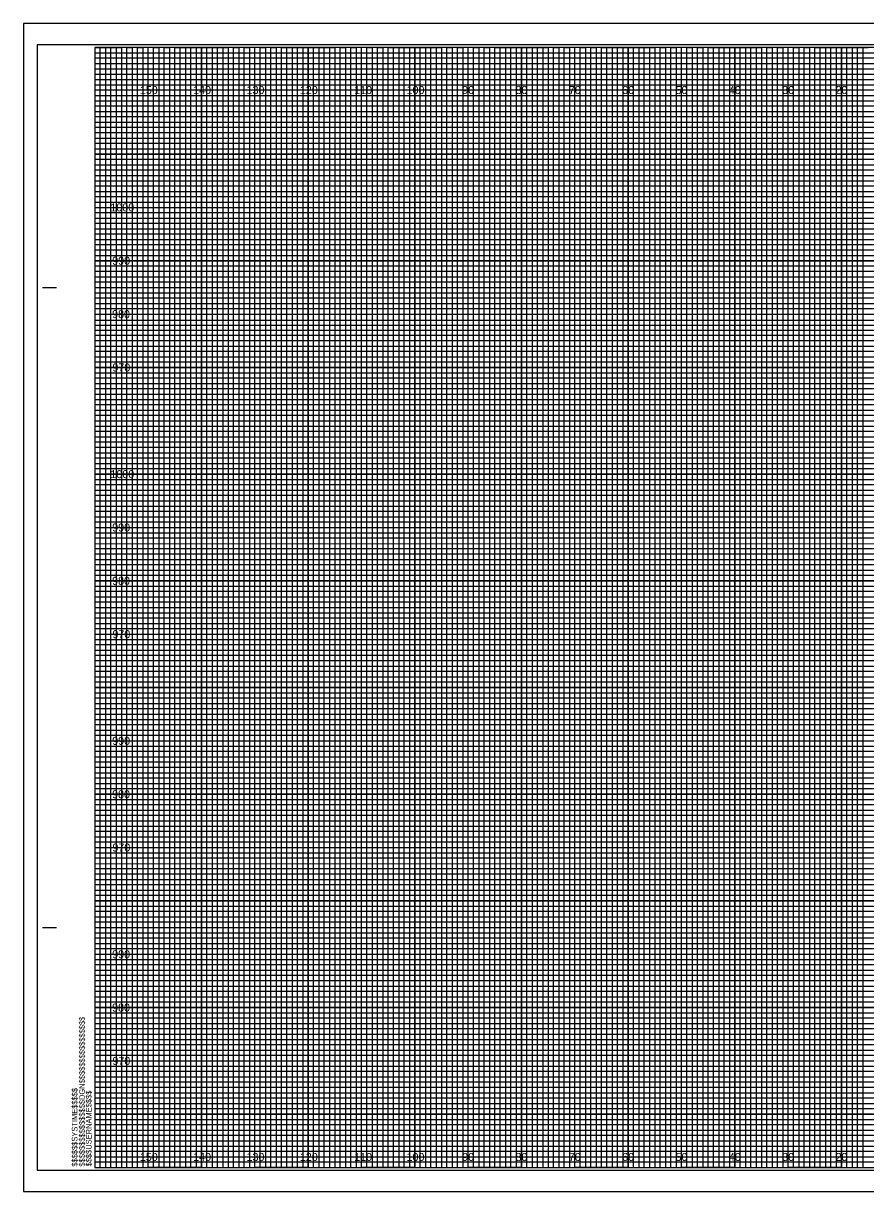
# Model space of a CAD drawing. Extents: x -13 to 323, y -5 to 215.
# Drawn here: x -13.4 to 144.5, y -4.5 to 214.5 of the extents above; entities that cross this region are included whole.
import ezdxf

# ---------------------------------------------------------------- set-up
doc = ezdxf.new("R2010")
doc.units = 0
for name, color, linetype in [('Prop XS Elevation Labels', 7, 'Continuous'), ('Prop XS Offset Labels', 7, 'Continuous'), ('Sheet Cross Section CELL', 7, 'Continuous'), ('Sheet Cross Section Grid Major CELL', 7, 'Continuous'), ('Sheet Cross Section Grid Middle CELL', 7, 'Continuous'), ('Sheet Cross Section Grid Minor 1 CELL', 7, 'Continuous'), ('Sheet Cross Section Grid Minor 2 CELL', 7, 'Continuous'), ('Sheet Cutting Line CELL', 7, 'Continuous'), ('Sheet DOT Grid CELL', 7, 'Continuous'), ('Sheet Plot Border Inside CELL', 7, 'Continuous'), ('Sheet Plot Border Outside CELL', 7, 'Continuous')]:
    doc.layers.add(name, color=color, linetype=linetype)

msp = doc.modelspace()

# ---------------------------------------------------------------- linework, layer by layer
at = {"layer": 'Sheet Cross Section CELL'}
for p, q in [((-9.8, 165), (-7.3, 165)), ((-9.7, 165), (-7.2, 165)), ((-9.8, 45), (-7.3, 45)), ((-9.7, 45), (-7.2, 45))]:
    msp.add_line(p, q, dxfattribs=at)
msp.add_lwpolyline([(320, 210), (0, 210), (0, 0), (320, 0)], close=True, dxfattribs=at)
at = {"layer": 'Sheet Cross Section Grid Major CELL'}
for p, q in [((10, 210), (0, 210)), ((10, 0), (10, 210)), ((30, 210), (20, 210)), ((20, 210), (20, 0)), ((30, 0), (30, 210)), ((50, 210), (40, 210)), ((40, 210), (40, 0)), ((50, 0), (50, 210)), ((70, 210), (60, 210)), ((60, 210), (60, 0)), ((70, 0), (70, 210)), ((90, 210), (80, 210)), ((80, 210), (80, 0)), ((90, 0), (90, 210)), ((110, 210), (100, 210)), ((100, 210), (100, 0)), ((110, 0), (110, 210)), ((130, 210), (120, 210)), ((120, 210), (120, 0)), ((130, 0), (130, 210)), ((150, 210), (140, 210)), ((140, 210), (140, 0)), ((20, 0), (10, 0)), ((40, 0), (30, 0)), ((60, 0), (50, 0)), ((80, 0), (70, 0)), ((100, 0), (90, 0)), ((120, 0), (110, 0)), ((140, 0), (130, 0))]:
    msp.add_line(p, q, dxfattribs=at)
for points in [[(0, 200), (320, 200), (320, 190), (0, 190)], [(0, 180), (320, 180), (320, 170), (0, 170)], [(0, 160), (320, 160), (320, 150), (0, 150)], [(0, 140), (320, 140), (320, 130), (0, 130)], [(0, 120), (320, 120), (320, 110), (0, 110)], [(0, 100), (320, 100), (320, 90), (0, 90)], [(0, 80), (320, 80), (320, 70), (0, 70)], [(0, 60), (320, 60), (320, 50), (0, 50)], [(0, 40), (320, 40), (320, 30), (0, 30)], [(0, 20), (320, 20), (320, 10), (0, 10)]]:
    msp.add_lwpolyline(points, dxfattribs=at)
at = {"layer": 'Sheet Cross Section Grid Middle CELL'}
for points in [[(0, 210), (5, 210), (5, 0), (15, 0), (15, 210), (25, 210), (25, 0), (35, 0), (35, 210), (45, 210), (45, 0), (55, 0), (55, 210), (65, 210), (65, 0), (75, 0), (75, 210), (85, 210), (85, 0), (95, 0), (95, 210), (105, 210), (105, 0), (115, 0), (115, 210), (125, 210), (125, 0), (135, 0), (135, 210), (145, 210)], [(0, 205), (275, 205)], [(0, 185), (320, 185), (320, 195), (0, 195)], [(0, 165), (320, 165), (320, 175), (0, 175)], [(0, 145), (320, 145), (320, 155), (0, 155)], [(0, 125), (320, 125), (320, 135), (0, 135)], [(0, 105), (320, 105), (320, 115), (0, 115)], [(0, 85), (320, 85), (320, 95), (0, 95)], [(0, 65), (320, 65), (320, 75), (0, 75)], [(0, 45), (320, 45), (320, 55), (0, 55)], [(0, 25), (320, 25), (320, 35), (0, 35)], [(0, 5), (320, 5), (320, 15), (0, 15)]]:
    msp.add_lwpolyline(points, dxfattribs=at)
at = {"layer": 'Sheet Cross Section Grid Minor 1 CELL'}
for p, q in [((0, 209), (260, 209)), ((260, 207.98), (0, 207.98)), ((0, 207.98), (0, 207)), ((0, 207), (260, 207)), ((260, 205.89), (0, 205.89)), ((0, 205.89), (0, 204)), ((0, 204), (320, 204))]:
    msp.add_line(p, q, dxfattribs=at)
for points in [[(0, 203), (270, 203), (320, 203), (320, 202), (0, 202)], [(0, 201), (320, 201), (320, 199), (0, 199)], [(0, 198), (320, 198), (320, 197), (0, 196.98)], [(0, 196), (320, 196), (320, 194), (0, 194)], [(0, 193), (320, 193), (320, 192), (0, 192)], [(0, 191), (320, 191), (320, 189), (0, 189)], [(0, 188), (320, 188), (320, 187), (0, 187)], [(0, 186), (320, 186), (320, 184), (0, 184)], [(0, 183), (320, 183), (320, 182), (0, 182)], [(0, 181), (320, 181), (320, 179), (0, 179)], [(0, 178), (320, 178), (320, 177), (0, 177)], [(0, 176), (320, 176), (320, 173.95), (320, 173), (320, 172), (0, 172)], [(0, 174), (320, 174), (320, 173), (0, 173)], [(0, 171), (320, 171), (320, 169), (0, 169.03)], [(0, 169.03), (320, 169), (320, 168), (0, 168)], [(0, 167), (320, 167), (320, 166), (0, 166)], [(0, 164), (320, 164), (320, 163), (0, 163)], [(0, 162), (320, 162), (320, 161), (0, 161)], [(-0.07, 158.89), (320, 158.89), (320, 157.88), (-0.07, 157.88)], [(0, 157), (320, 157), (320, 156), (0, 156)], [(0, 154), (320, 154), (320, 153), (0, 153)], [(0, 152), (320, 152), (320, 151), (0, 151)], [(0, 149), (320, 149), (320, 148), (0, 148)], [(0, 147), (320, 147), (320, 146), (0, 146)], [(0, 144), (320, 144), (320, 143), (0, 143)], [(0, 142), (320, 142), (320, 141), (0, 141)], [(0, 139), (320, 139), (319.99, 137.98), (0, 138)], [(0, 137), (320, 137), (320, 136), (0, 136)], [(0, 134), (320, 134), (320, 133), (0, 133)], [(0, 132), (320, 132), (320, 131), (0, 131)], [(0, 129), (320, 129), (320, 128), (0, 128)], [(0, 127), (320, 127), (320, 126), (0, 126)], [(0, 124), (320, 124), (320, 123), (0, 123)], [(0, 122), (320, 122), (320, 121), (0, 121)], [(0, 119), (320, 119), (320, 118), (0, 118)], [(0, 116.99), (320.07, 116.91), (320, 116), (0, 116)], [(0, 114), (320, 114), (320, 113), (0, 113)], [(0, 112), (320, 112), (320, 111), (0, 111)], [(0, 109), (320, 109), (320, 108), (0, 108)], [(0, 107), (320, 107), (320, 106), (0, 106)], [(0, 104), (320, 104), (320, 103), (0, 103)], [(0, 102), (320, 102), (320, 101), (0, 101)], [(0, 99), (320, 99), (320, 98), (0, 98)], [(0, 97), (320, 97), (320, 96), (0, 96)], [(0, 94), (320, 94), (320, 93), (0, 93)], [(0, 92), (320, 92), (320, 91), (0, 91)], [(0, 89), (320, 89), (320, 88), (0, 88)], [(0, 87), (320, 87), (320, 86), (0, 86)], [(0, 84), (320, 84), (320, 83), (0, 83)], [(0, 82), (320, 82), (320, 81), (0, 81)], [(0, 79), (320, 79), (319.99, 77.98), (0, 78)], [(0, 77), (320, 77), (320, 76), (0, 76)], [(0, 74), (320, 74), (320, 73), (0, 73)], [(0, 72), (320, 72), (320, 71), (0, 71)], [(0, 69), (320, 69), (320, 68), (0, 68)], [(0, 67), (320, 67), (320, 66), (0, 66)], [(0, 64), (320, 64), (320, 63), (0, 63)], [(0, 62), (320, 62), (320, 61), (0, 61)], [(0, 59), (320, 59), (320, 58), (0, 58)], [(0, 56.99), (320.07, 56.91), (320, 56), (0, 56)], [(0, 54), (320, 54), (320, 53), (0, 53)], [(0, 52), (320, 52), (320, 51), (0, 51)], [(0, 49), (320, 49), (320, 48), (0, 48)], [(0, 47), (320, 47), (320, 46), (0, 46)], [(0, 44), (320, 44), (320, 43), (0, 43)], [(0, 42), (320, 42), (320, 41), (0, 41)], [(0, 39), (320, 39), (320, 38), (0, 38)], [(0, 37), (320, 37), (320, 36), (0, 36)], [(0, 34), (320, 34), (320, 33), (0, 33)], [(0, 32), (320, 32), (320, 31), (0, 31)], [(0, 29), (320, 29), (320, 28), (0, 28)], [(0, 27), (320, 27), (320, 26), (0, 26)], [(0, 24), (320, 24), (320, 23), (0, 23)], [(0, 22), (320, 22), (320, 21), (0, 21)], [(0, 19), (320, 19), (320, 18), (0, 18)], [(0, 17), (320, 17), (320, 16), (0, 16)], [(0, 14), (320, 14), (320, 13), (0, 13)], [(0, 12), (320, 12), (320, 11), (0, 11)], [(0, 9), (320, 9), (320, 8), (0, 8)], [(0, 7), (320, 7), (320, 6), (0, 6)], [(0, 4), (320, 4), (320, 3), (0, 3)], [(0, 2), (320, 2), (320, 1), (0, 1)]]:
    msp.add_lwpolyline(points, dxfattribs=at)
at = {"layer": 'Sheet Cross Section Grid Minor 2 CELL'}
for points in [[(0, 0), (1, 0), (1, 210), (2, 210), (2, 0)], [(2, 0), (3, 0), (3, 210), (4, 210), (4, 0)], [(5, 0), (6, 0), (6, 210), (7, 210), (7, 0)], [(7, 0), (8, 0), (8, 210), (9, 210), (9, 0)], [(10, 0), (11, 0), (11, 210), (12, 210), (12, 0)], [(12, 0), (13, 0), (13, 210), (14, 210), (14, 0)], [(15, 0), (16, 0), (16, 210), (17, 210), (17, 0)], [(17, 0), (18, 0), (18, 210), (19, 210), (19, 0)], [(20, 0), (21, 0), (21, 210), (22, 210), (22, 0)], [(22, 0), (23, 0), (23, 210), (24, 210), (24, 0)], [(25, 0), (26, 0), (26, 210), (27, 210), (27, 0)], [(27, 0), (28, 0), (28, 210), (29, 210), (29, 0)], [(30, 0), (31, 0), (31, 210), (32, 210), (32, 0)], [(32, 0), (33, 0), (33, 210), (34, 210), (34, 0)], [(35, 0), (36, 0), (36, 210), (37, 210), (37, 0)], [(37, 0), (38, 0), (38, 210), (39, 210), (39, 0)], [(40, 0), (41, 0), (41, 210), (42, 210), (42, 0)], [(42, 0), (43, 0), (43, 210), (44, 210), (44, 0)], [(45, 0), (46, 0), (46, 210), (47, 210), (47, 0)], [(47, 0), (48, 0), (48, 210), (49, 210), (49, 0)], [(50, 0), (51, 0), (51, 210), (52, 210), (52, 0)], [(52, 0), (53, 0), (53, 210), (54, 210), (54, 0)], [(55, 0), (56, 0), (56, 210), (57, 210), (57, 0)], [(57, 0), (58, 0), (58, 210), (59, 210), (59, 0)], [(60, 0), (61, 0), (61, 210), (62, 210), (62, 0)], [(62, 0), (63, 0), (63, 210), (64, 210), (64, 0)], [(65, 0), (66, 0), (66, 210), (67, 210), (67, 0)], [(67, 0), (68, 0), (68, 210), (69, 210), (69, 0)], [(70, 0), (71, 0), (71, 210), (72, 210), (72, 0)], [(72, 0), (73, 0), (73, 210), (74, 210), (74, 0)], [(75, 0), (76, 0), (76, 210), (77, 210), (77, 0)], [(77, 0), (78, 0), (78, 210), (79, 210), (79, 0)], [(80, 0), (81, 0), (81, 210), (82, 210), (82, 0)], [(82, 0), (83, 0), (83, 210), (84, 210), (84, 0)], [(85, 0), (86, 0), (86, 210), (87, 210), (87, 0)], [(87, 0), (88, 0), (88, 210), (89, 210), (89, 0)], [(90, 0), (91, 0), (91, 210), (92, 210), (92, 0)], [(92, 0), (93, 0), (93, 210), (94, 210), (94, 0)], [(95, 0), (96, 0), (96, 210), (97, 210), (97, 0)], [(97, 0), (98, 0), (98, 210), (99, 210), (99, 0)], [(100, 0), (101, 0), (101, 210), (102, 210), (102, 0)], [(102, 0), (103, 0), (103, 210), (104, 210), (104, 0)], [(105, 0), (106, 0), (106, 210), (107, 210), (107, 0)], [(107, 0), (108, 0), (108, 210), (109, 210), (109, 0)], [(110, 0), (111, 0), (111, 210), (112, 210), (112, 0)], [(112, 0), (113, 0), (113, 210), (114, 210), (114, 0)], [(115, 0), (116, 0), (116, 210), (117, 210), (117, 0)], [(117, 0), (118, 0), (118, 210), (119, 210), (119, 0)], [(120, 0), (121, 0), (121, 210), (122, 210), (122, 0)], [(122, 0), (123, 0), (123, 210), (124, 210), (124, 0)], [(125, 0), (126, 0), (126, 210), (127, 210), (127, 0)], [(127, 0), (128, 0), (128, 210), (129, 210), (129, 0)], [(130, 0), (131, 0), (131, 210), (132, 210), (132, 0)], [(132, 0), (133, 0), (133, 210), (134, 210), (134, 0)], [(135, 0), (136, 0), (136, 210), (137, 210), (137, 0)], [(137, 0), (138, 0), (138, 210), (139, 210), (139, 0)], [(140, 0), (141, 0), (141, 210), (142, 210), (142, 0)], [(142, 0), (143, 0), (143, 210), (144, 210), (144, 0)]]:
    msp.add_lwpolyline(points, dxfattribs=at)
at = {"layer": 'Sheet Cutting Line CELL'}
for p, q in [((323.3, 214.5), (-13.4, 214.5)), ((-13.4, 214.5), (-13.4, -4.5)), ((-13.4, -4.5), (323.3, -4.5))]:
    msp.add_line(p, q, dxfattribs=at)
at = {"layer": 'Sheet DOT Grid CELL'}
for p, q in [((10, 0), (10, 210)), ((20, 0), (20, 210)), ((30, 0), (30, 210)), ((40, 0), (40, 210)), ((50, 0), (50, 210)), ((60, 0), (60, 210)), ((70, 0), (70, 210)), ((80, 0), (80, 210)), ((90, 0), (90, 210)), ((100, 0), (100, 210)), ((110, 0), (110, 210)), ((120, 0), (120, 210)), ((130, 0), (130, 210)), ((140, 0), (140, 210)), ((0, 200), (320, 200)), ((0, 190), (320, 190)), ((0, 180), (320, 180)), ((0, 170), (320, 170)), ((0, 160), (320, 160)), ((0, 150), (320, 150)), ((0, 140), (320, 140)), ((0, 130), (320, 130)), ((0, 120), (320, 120)), ((0, 110), (320, 110)), ((0, 100), (320, 100)), ((0, 90), (320, 90)), ((0, 80), (320, 80)), ((0, 70), (320, 70)), ((0, 60), (320, 60)), ((0, 50), (320, 50)), ((0, 40), (320, 40)), ((0, 30), (320, 30)), ((0, 20), (320, 20)), ((0, 10), (320, 10))]:
    msp.add_line(p, q, dxfattribs=at)
at = {"layer": 'Sheet Plot Border Inside CELL'}
msp.add_lwpolyline([(-10.8, -0.5), (322.4, -0.5), (322.4, 210.5), (-10.8, 210.5)], close=True, dxfattribs=at)
at = {"layer": 'Sheet Plot Border Outside CELL'}
msp.add_lwpolyline([(-13.4, -4.5), (323.3, -4.5), (323.3, 214.5), (-13.4, 214.5)], close=True, dxfattribs=at)

# ---------------------------------------------------------------- texts
at = {"layer": 'Prop XS Elevation Labels'}
for s, p in [('1000', (2.92, 179.25)), ('990', (3.26, 169.25)), ('980', (3.24, 159.25)), ('970', (3.3, 149.25)), ('1000', (2.92, 129.25)), ('990', (3.26, 119.25)), ('980', (3.24, 109.25)), ('970', (3.3, 99.25)), ('990', (3.26, 79.25)), ('980', (3.24, 69.25)), ('970', (3.3, 59.25)), ('990', (3.26, 39.25)), ('980', (3.24, 29.25)), ('970', (3.3, 19.25))]:
    msp.add_text(s, height=1.5, dxfattribs=at).set_placement(p)
at = {"layer": 'Prop XS Offset Labels'}
for s, p in [('150', (8.44, 201.25)), ('140', (18.44, 201.25)), ('130', (28.44, 201.25)), ('120', (38.44, 201.25)), ('110', (48.62, 201.25)), ('100', (58.44, 201.25)), ('90', (68.86, 201.25)), ('80', (78.86, 201.25)), ('70', (88.86, 201.25)), ('60', (98.86, 201.25)), ('50', (108.86, 201.25)), ('40', (118.86, 201.25)), ('30', (128.86, 201.25)), ('20', (138.86, 201.25)), ('150', (8.44, 1.25)), ('140', (18.44, 1.25)), ('130', (28.44, 1.25)), ('120', (38.44, 1.25)), ('110', (48.62, 1.25)), ('100', (58.44, 1.25)), ('90', (68.86, 1.25)), ('80', (78.86, 1.25)), ('70', (88.86, 1.25)), ('60', (98.86, 1.25)), ('50', (108.86, 1.25)), ('40', (118.86, 1.25)), ('30', (128.86, 1.25)), ('20', (138.86, 1.25))]:
    msp.add_text(s, height=1.5, dxfattribs=at).set_placement(p)
at = {"layer": 'Sheet Cross Section CELL'}
for s, p in [('$$$$$$$$$$$$$$$$DGN$$$$$$$$$$$$$$$$', (-1.88, 0.18)), ('$$$$$$SYSTIME$$$$$', (-3.26, 0.18)), ('$$$$USERNAME$$$$', (-0.62, 0.23))]:
    msp.add_text(s, height=1.05, rotation=90, dxfattribs=at).set_placement(p)

doc.saveas('drawing.dxf')
